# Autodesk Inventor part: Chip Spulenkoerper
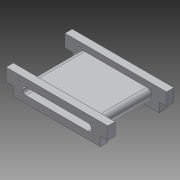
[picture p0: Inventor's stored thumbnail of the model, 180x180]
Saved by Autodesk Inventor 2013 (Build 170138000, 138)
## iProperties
Created: 2012-07
Part Number: Chip Spulenkoerper
Material: PC/ABS-Kunststoff
Document SubType Name: Modeling
Designer: rYan
Mass: 8.63636 g
Surface Area: 83.1434 cm^2
Volume: 5.78457 cm^3
Density: 1.493 g/cm^3
Author: rYan
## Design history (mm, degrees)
sketch "Skizze1"
  geometry: L1 (-19.75, 2.75)-(19.75, 2.75); L2 (19.75, 2.75)-(19.75, -2.75); L3 (19.75, -2.75)-(-19.75, -2.75); L4 (-19.75, -2.75)-(-19.75, 2.75); L5 (0, -3.85)-(0, 3.85) reference; L6 (-27.65, 0)-(27.65, 0) reference; 1 further point
  constraints: 8 end point, 2 parallel, 1 horizontal, 1 perpendicular, 2 other
  dimensions: "d0" = 5.5 distance of L1.end L2.end; "d2" = 39.5 distance of L1.start L1.end
extrude "Extrusion1" new body sketch "Skizze1" distance "d3" = 28.4; taper "d4" = 0 deg
sketch "Skizze2"
  geometry: L1 (-28, 6)-(28, 6); L2 (28, 6)-(28, -1); L3 (-28, -1)-(-28, 6); L4 (-23.9, -1)-(-23.9, -6); L5 (-23.9, -6)-(23.9, -6); L6 (23.9, -6)-(23.9, -1); L7 (28, -1)-(23.9, -1); L8 (-23.9, -1)-(-28, -1); L9 (0, 8.4)-(0, -8.4) reference; L10 (-40.6, 0)-(40.6, 0) reference; 1 further point
  constraints: 16 end point, 4 parallel, 1 horizontal, 1 perpendicular, 4 other
  dimensions: "d5" = 7 distance of L1.end L2.end; "d7" = 5 distance of L5.end L6.end; "d8" = 4.1 distance between parallel lines of L6 L2; "d9" = 47.8 distance of L4.end L5.end
extrude "Extrusion2" join sketch "Skizze2" distance "d10" = 4; taper "d11" = 0 deg
workplane "Arbeitsebene1"
mirror "Spiegeln1"
sketch "Skizze3"
  geometry: L1 (-39.2, 0)-(39.2, 0) reference; L2 (-17, 2)-(17, 2); L3 (17, -2)-(-17, -2); L4 (0, 8.4)-(0, -8.4) reference; A1 r 2 centre (-17, 0) between (-17, 2) and (-17, -2); A2 r 2 centre (17, 0) between (17, -2) and (17, 2); 1 further point
  constraints: 4 end point, 4 point on circle, 4 tangent, 2 centre point, 2 parallel, 1 point on line, 1 symmetric about line
  dimensions: "d12" = 4 distance between parallel lines of L3 L2; "d14" = 34 distance of A2.centre A1.centre
extrude "Extrusion3" cut sketch "Skizze3" stored distance "d15" = 4; taper "d16" = 0 deg
fillet "Rundung1" dims "d17" = 2.75
sketch "Sketch4"
  geometry: L1 (0, 8.4)-(0, -8.4) reference; L2 (-39.2, 0)-(39.2, 0) reference; 3 further points
  constraints: 1 symmetric about line
  dimensions: "d18" = 40 distance of point (20, 3) point (-20, 3); "d20" = 3 distance from line of point (-20, 3) L2
hole "Hole1" sketch "Sketch4" at (-20, 3), (20, 3) diameter "d21" = 1; stored, may be unused: countersink angle "d25" = 90 deg, drill point angle "d27" = 118 deg; dims "d22" = 6, "d23" = 4, "d24" = 2, "d26" = 8
node "Volumenkörper1"
